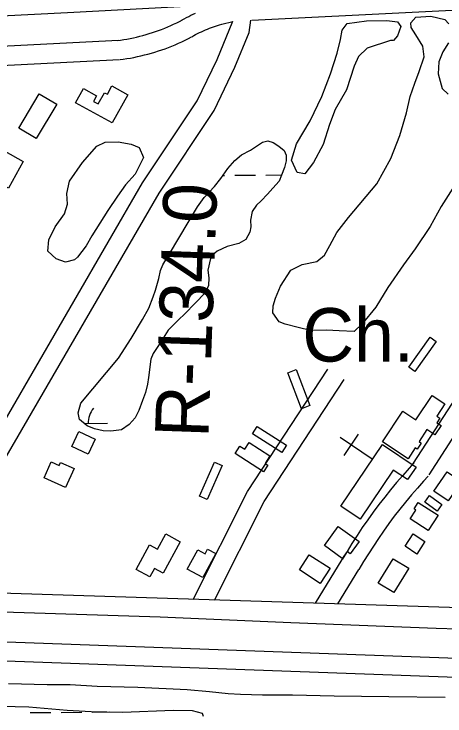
# Model space of a CAD drawing. Extents: x 3540316 to 3578335, y 553172 to 578787.
# Drawn here: x 3546594 to 3547262, y 568493 to 569583 of the extents above; entities that cross this region are included whole.
import ezdxf

# ---------------------------------------------------------------- set-up
doc = ezdxf.new("R2010")
doc.units = 0
for name, color, linetype in [('V-BLDG-OTLN', 7, 'Continuous'), ('V-LEVE-TOET', 7, 'Continuous'), ('V-RAIL-TRAK', 7, 'Continuous'), ('V-RIVR-RANG-IDEN', 7, 'Continuous'), ('V-ROAD-CNTR', 7, 'Continuous'), ('V-SITE-OTLN', 7, 'Continuous'), ('V-SITE-OTLN-IDEN', 7, 'Continuous'), ('V-SITE-VEGE', 7, 'Continuous'), ('V-SURV-LINE', 7, 'Continuous'), ('V-WETL-SWMP', 7, 'Continuous')]:
    doc.layers.add(name, color=color, linetype=linetype)

msp = doc.modelspace()

# ---------------------------------------------------------------- linework, layer by layer
at = {"layer": 'V-BLDG-OTLN'}
for points in [[(3546770.6, 569457.3), (3546746.3, 569413.5), (3546689.5, 569444.9), (3546701.7, 569467.1), (3546722.2, 569455.7), (3546717.4, 569447), (3546724.6, 569443), (3546734.3, 569460.5), (3546738.9, 569458), (3546746, 569470.9)], [(3546660.5, 569442.7), (3546628.6, 569389.2), (3546601.6, 569405.4), (3546633.4, 569458.8)], [(3546608.5, 569353.6), (3546585.7, 569312.4), (3546556.9, 569328.4), (3546579.8, 569369.5)], [(3547248.7, 569074.3), (3547215.5, 569027.7), (3547206.4, 569034.2), (3547239.6, 569080.8)], [(3547031.9, 569030.6), (3547053, 568974.8), (3547039.9, 568969.9), (3547018.9, 569025.7)], [(3547205.2, 568892.3), (3547165.5, 568918.6), (3547197, 568966.3), (3547217.4, 568952.8), (3547242.4, 568990.5), (3547262.3, 568977.3), (3547249.8, 568958.4), (3547254.5, 568955.3), (3547249.9, 568948.2), (3547256.5, 568943.8), (3547246.9, 568929.3), (3547234.5, 568937.5), (3547222.3, 568919), (3547225.8, 568916.6), (3547219.3, 568906.9), (3547216.3, 568909)], [(3546720, 568922.7), (3546708.9, 568899.4), (3546683.8, 568911.3), (3546694.9, 568934.7)], [(3547009.4, 568902.1), (3546964.1, 568931.2), (3546971.2, 568942.3), (3547016.5, 568913.2)], [(3546981, 568872), (3546937.2, 568900.4), (3546944.6, 568911.9), (3546952.1, 568907.1), (3546958.9, 568917.6), (3546991.1, 568896.8), (3546983.4, 568885), (3546987.7, 568882.3)], [(3547101.1, 568818.5), (3547165.5, 568914.5), (3547217.7, 568879.4), (3547204.6, 568859.9), (3547182.4, 568874.7), (3547131.2, 568798.3)], [(3546640.7, 568862.6), (3546651.8, 568887.3), (3546664.1, 568881.7), (3546666.4, 568886.7), (3546687.5, 568877.2), (3546674.1, 568847.5)], [(3546917.1, 568881.9), (3546893.5, 568829.1), (3546881.7, 568834.4), (3546905.3, 568887.2)], [(3547288.3, 568856.9), (3547267.5, 568826.7), (3547245.4, 568842), (3547266.1, 568872.1)], [(3547250.2, 568811), (3547231.1, 568824.8), (3547238.4, 568835.1), (3547257.6, 568821.2)], [(3547236.4, 568780.8), (3547208.3, 568798.8), (3547217.2, 568812.7), (3547214.6, 568814.4), (3547221.1, 568824.6), (3547251.8, 568804.9)], [(3547102.8, 568737.4), (3547075.4, 568757.5), (3547097.1, 568787.2), (3547129.3, 568763.6), (3547115.5, 568744.6), (3547110.7, 568748.2)], [(3546852, 568763.3), (3546825.6, 568714.6), (3546812.1, 568721.9), (3546805, 568708.8), (3546783.7, 568720.3), (3546804.4, 568758.5), (3546816.6, 568751.9), (3546829.4, 568775.5)], [(3547231.5, 568763.6), (3547219, 568744.4), (3547200.6, 568756.4), (3547213.1, 568775.6)], [(3546906.9, 568745.2), (3546886.8, 568708.1), (3546862.8, 568721.1), (3546879.1, 568751.1), (3546890.6, 568744.9), (3546894.4, 568751.9)], [(3547051.9, 568743.1), (3547084.2, 568722.4), (3547069, 568698.8), (3547036.8, 568719.6)], [(3547159, 568699.3), (3547181.9, 568737), (3547206.2, 568722.2), (3547183.4, 568684.5)]]:
    msp.add_lwpolyline(points, close=True, dxfattribs=at)
at = {"layer": 'V-LEVE-TOET'}
for points in [[(3547740.4, 568609.2), (3547603, 568614.6), (3547416.9, 568623.7), (3547248.7, 568628.6), (3547023.7, 568637.8), (3546820.6, 568646.2), (3546577.1, 568654.2), (3546379.4, 568658.5), (3546116.1, 568667.9), (3546052.5, 568669.6), (3545807.7, 568677.5), (3545748.9, 568677.1), (3545669.5, 568674.1), (3545560.7, 568664.3), (3545380.7, 568652.1), (3545183, 568637.3), (3545015.3, 568626.4), (3544792.3, 568613.1), (3544595.9, 568600.3), (3544446.6, 568588.6)], [(3546585.6, 568543.6), (3546645.8, 568541.9), (3546681.4, 568541.8), (3546723.1, 568539.5), (3546786, 568537.9), (3546862.6, 568534.1), (3546897.5, 568531.2), (3546926.2, 568527.7), (3546945.4, 568526.9), (3546979.6, 568526), (3547026.1, 568525.8), (3547090.4, 568524.2), (3547175.2, 568523.1), (3547262.7, 568522)]]:
    msp.add_lwpolyline(points, dxfattribs=at)
at = {"layer": 'V-RAIL-TRAK'}
msp.add_lwpolyline([(3544440.2, 569467.6), (3544499.8, 569470.6), (3544650.3, 569478.1), (3544767.7, 569484.7), (3544854.2, 569489.5), (3545075.2, 569500.8), (3545365.9, 569515.9), (3545593.8, 569528.5), (3545806.6, 569539.9), (3545830.1, 569541.1), (3546063.1, 569553.1), (3546369.7, 569569.5), (3546676.9, 569585.2), (3546997.1, 569602.2), (3547359.7, 569620.4), (3547619, 569632.9), (3547707.6, 569637.2)], dxfattribs=at)
at = {"layer": 'V-ROAD-CNTR'}
for points in [[(3546963.1, 569573.3), (3547470.5, 569598.4)], [(3546855, 569573.4), (3546858.2, 569575.2), (3546861.6, 569577.1), (3546865.1, 569578.9), (3546868.5, 569580.6), (3546872, 569582.3), (3546875.6, 569583.9)], [(3546427.1, 568688.2), (3546580.5, 568952), (3546793.6, 569320.3), (3546878.4, 569447.9), (3546909.3, 569512.2), (3546933.5, 569571.5)], [(3546461.2, 568687.1), (3546606.5, 568937), (3546819.1, 569304.5), (3546904.6, 569433), (3546936.7, 569500.1), (3546958.7, 569553.9), (3546961.3, 569573.2)], [(3546755, 569541.7), (3546759.3, 569542.2), (3546764.3, 569543), (3546769.3, 569543.8), (3546774.3, 569544.8), (3546779.3, 569545.8), (3546784.2, 569546.9), (3546789.2, 569548.1), (3546794.1, 569549.4), (3546799, 569550.7), (3546803.8, 569552.2), (3546808.7, 569553.7), (3546813.5, 569555.4), (3546818.3, 569557), (3546823, 569558.8), (3546827.8, 569560.7), (3546832.5, 569562.7), (3546837.1, 569564.7), (3546841.7, 569566.8), (3546846.4, 569569), (3546850.9, 569571.2), (3546855.5, 569573.7)], [(3546869.9, 569547.4), (3546872.8, 569549), (3546875.7, 569550.6), (3546878.7, 569552.2), (3546881.7, 569553.7), (3546884.8, 569555.1), (3546887.8, 569556.5), (3546890.9, 569557.9), (3546894, 569559.2), (3546897.1, 569560.4), (3546900.3, 569561.6), (3546903.4, 569562.7), (3546906.6, 569563.8), (3546909.8, 569564.8), (3546913, 569565.7), (3546916.3, 569566.7), (3546933.3, 569571.1)], [(3544779, 569435.5), (3546311.5, 569519), (3546756.2, 569541.8)], [(3546759, 569511.9), (3546763.5, 569512.5), (3546769, 569513.4), (3546774.6, 569514.3), (3546780.1, 569515.3), (3546785.6, 569516.5), (3546791, 569517.7), (3546796.4, 569519), (3546801.9, 569520.4), (3546807.3, 569521.9), (3546812.7, 569523.5), (3546818, 569525.2), (3546823.3, 569527), (3546828.6, 569528.8), (3546833.9, 569530.8), (3546839.1, 569532.9), (3546844.2, 569535), (3546849.4, 569537.3), (3546854.5, 569539.6), (3546859.5, 569542), (3546864.5, 569544.5), (3546869.4, 569547.1)], [(3546492.7, 569498.3), (3546757.8, 569511.8)], [(3547212.8, 568883.7), (3547274, 568978.7), (3547337.1, 569071.9), (3547340.9, 569077.3)], [(3547238, 568867.4), (3547299, 568962.2), (3547361.8, 569054.8), (3547365.5, 569060.1)], [(3546872, 568674), (3546956.2, 568841.2), (3547080.9, 569031.5)], [(3546905, 568672.9), (3546982.3, 568826.1), (3547106, 569015.1)], [(3547214.4, 568885.7), (3547206.8, 568877.5), (3547197.1, 568866.5), (3547187.5, 568855.4), (3547178.1, 568844.1), (3547169, 568832.7), (3547160, 568821.1), (3547151.2, 568809.2), (3547142.7, 568797.4), (3547134.3, 568785.3), (3547126.2, 568773), (3547118.3, 568760.8), (3547110.6, 568748.3), (3547103.2, 568735.7)], [(3547236.4, 568865.4), (3547229, 568857.4), (3547219.7, 568846.8), (3547210.4, 568836.1), (3547201.4, 568825.1), (3547192.5, 568814.1), (3547183.9, 568803), (3547175.5, 568791.6), (3547167.2, 568780.1), (3547159.2, 568768.5), (3547151.4, 568756.6), (3547143.7, 568744.7), (3547136.3, 568732.8), (3547129, 568720.5)], [(3547061.6, 568668), (3547103.3, 568735.9)], [(3547096.1, 568666.9), (3547128.9, 568720.2)], [(3548203.3, 568619.8), (3547285.4, 568660.8), (3545892.6, 568705.2)]]:
    msp.add_lwpolyline(points, dxfattribs=at)
at = {"layer": 'V-SITE-OTLN'}
for p, q in [((3547149.7, 568891.5), (3547100.2, 568925.3)), ((3547127.9, 568930.6), (3547105.4, 568897.5))]:
    msp.add_line(p, q, dxfattribs=at)
at = {"layer": 'V-SITE-VEGE'}
for points in [[(3547278.3, 569317.8), (3547256.7, 569284), (3547239.3, 569253), (3547216.4, 569217.9), (3547198.3, 569193.1), (3547174, 569158), (3547155.2, 569127.7), (3547134.3, 569101.5), (3547121.8, 569089.9), (3547098.4, 569090.7), (3547079, 569092.1), (3547054.2, 569091.5), (3547034.8, 569095.8), (3547014.8, 569101.4), (3547005.2, 569104.9), (3546995.6, 569118.8), (3546996.3, 569129.8), (3546999.8, 569141.5), (3547007.5, 569160.1), (3547023.5, 569184.9), (3547040.8, 569193.8), (3547063.6, 569198.6), (3547075.4, 569208.2), (3547083.8, 569223.3), (3547094.9, 569243.3), (3547113, 569266.7), (3547156.7, 569319), (3547178.3, 569358.3), (3547192.3, 569394.1), (3547202.8, 569429.3), (3547208.5, 569454.8), (3547215.5, 569475.5), (3547222.4, 569493.5), (3547230.1, 569516.2), (3547228.2, 569532.8), (3547217.2, 569550.1), (3547210.3, 569561.9), (3547209.7, 569568.8), (3547217.3, 569577.7), (3547240.8, 569579), (3547262.2, 569574.1), (3547268.4, 569567.1)], [(3547268.2, 569538.1), (3547259.2, 569523.7), (3547252.9, 569508.5), (3547252.1, 569489.9), (3547258.2, 569467), (3547267.2, 569458)]]:
    msp.add_lwpolyline(points, dxfattribs=at)
for points in [[(3547177.8, 569541.3), (3547141.8, 569529.7), (3547128.6, 569516.7), (3547121.6, 569501.5), (3547109.7, 569465), (3547092.3, 569434.6), (3547083.2, 569411.2), (3547073.4, 569380.2), (3547058.8, 569351.9), (3547044.9, 569334.7), (3547033.2, 569336.8), (3547024.3, 569355.5), (3547032, 569381), (3547053.6, 569416.9), (3547071.7, 569454.8), (3547085, 569489.9), (3547095.5, 569521.7), (3547100.4, 569543), (3547103.3, 569557.5), (3547110.9, 569567.9), (3547140.6, 569571.9), (3547172.4, 569572.4), (3547189, 569570.3), (3547193.8, 569563.3), (3547188.9, 569548.9), (3547182.6, 569541.3)], [(3546795, 569360), (3546781.8, 569333.8), (3546767.2, 569317.3), (3546754.7, 569300.1), (3546739.4, 569277.4), (3546715, 569238.1), (3546706, 569223), (3546692.8, 569205.1), (3546687.9, 569201), (3546674.1, 569197.6), (3546659.6, 569202.5), (3546646.5, 569214.3), (3546648, 569232.2), (3546657.8, 569252.2), (3546672.3, 569272.2), (3546677.3, 569287.3), (3546675.9, 569303.9), (3546680.2, 569323.2), (3546700.3, 569352.2), (3546722.6, 569377.6), (3546735.7, 569383.8), (3546755.7, 569384.4), (3546775.8, 569380.8), (3546788.2, 569375.2)]]:
    msp.add_lwpolyline(points, close=True, dxfattribs=at)
at = {"layer": 'V-SURV-LINE'}
for points in [[(3545755.6, 568637.9), (3548250.8, 568547.7)], [(3548249.7, 568517.8), (3545754.5, 568607.9)]]:
    msp.add_lwpolyline(points, dxfattribs=at)
at = {"layer": 'V-WETL-SWMP'}
for p, q in [((3546918.2, 569332.1), (3546920.8, 569332.1)), ((3546936.8, 569332.2), (3546968.8, 569332.5)), ((3546984.8, 569332.6), (3547009.1, 569332.8)), ((3546703.1, 568947), (3546739.1, 568947.3)), ((3546619.2, 568498.3), (3546651.2, 568498.5)), ((3546667.2, 568498.6), (3546699.2, 568498.9)), ((3546715.2, 568499), (3546742.1, 568499.2))]:
    msp.add_line(p, q, dxfattribs=at)
msp.add_lwpolyline([(3546806.2, 569046.9), (3546802.6, 569018.5), (3546801.2, 569008.1), (3546798.3, 568995), (3546793.4, 568982.5), (3546787.8, 568967.3), (3546782.2, 568955.6), (3546772.5, 568945.2), (3546760.7, 568937), (3546744.1, 568935), (3546732.3, 568935.7), (3546719.1, 568938.6), (3546707.4, 568943.5), (3546695.7, 568953.2), (3546693.6, 568963.6), (3546697.9, 568978.8), (3546756.3, 569048.5), (3546775.9, 569078.8), (3546793.3, 569108.5), (3546803.1, 569125.8), (3546810.1, 569143.8), (3546813.6, 569154.1), (3546818.5, 569172.1), (3546821.3, 569184.6), (3546824.8, 569193.5), (3546835.3, 569210.1), (3546878.6, 569283.3), (3546889, 569297.8), (3546905, 569315), (3546914.8, 569327.4), (3546925.9, 569342.6), (3546936.4, 569355), (3546946.8, 569364), (3546960.7, 569371.5), (3546979.4, 569383.9), (3546987.7, 569386), (3546996, 569383.1), (3547005, 569377.6), (3547013.3, 569370.6), (3547016, 569363.7), (3547016, 569354.7), (3547013.8, 569344.3), (3547008.9, 569332.6), (3547005.4, 569322.9), (3546995.7, 569312.5), (3546987.3, 569302.9), (3546977.6, 569292.5), (3546970, 569285.7), (3546963.7, 569276), (3546960.9, 569262.8), (3546961.5, 569252.5), (3546960.1, 569244.2), (3546953.8, 569232.4), (3546942.7, 569226.2), (3546924.7, 569221.5), (3546909.4, 569214.6), (3546901.8, 569208.4), (3546899, 569202.9), (3546894.7, 569184.9), (3546896.1, 569173.1), (3546896, 569161.4), (3546891.1, 569150.3), (3546874.4, 569133.1), (3546859.8, 569117.9), (3546848.7, 569107.6), (3546833.4, 569091.7), (3546820.1, 569071), (3546809.7, 569055.8)], close=True, dxfattribs=at)
msp.add_lwpolyline([(3546014, 568521.4), (3546059.1, 568515), (3546099.4, 568511.4), (3546139.1, 568511.9), (3546187.7, 568515.8), (3546262.9, 568516.1), (3546363.5, 568512.3), (3546446.2, 568511.9), (3546531.7, 568509.4), (3546617.2, 568507), (3546676.7, 568501.9), (3546713.6, 568499.7), (3546762.9, 568498.8), (3546840.9, 568501.9), (3546870.3, 568501.7), (3546886, 568497.6), (3546887.3, 568492.8)], dxfattribs=at)
msp.add_arc((3546744.4, 568947.8), 35.2, 139.6699, 181.2135, dxfattribs=at)

# ---------------------------------------------------------------- texts
at = {"layer": 'V-RIVR-RANG-IDEN'}
msp.add_text('R-134.0', height=83, rotation=87.9832, dxfattribs=at).set_placement((3546895.5, 568924))
at = {"layer": 'V-SITE-OTLN-IDEN'}
msp.add_text('Ch.', height=83, dxfattribs=at).set_placement((3547041.3, 569043.1))

doc.saveas('drawing.dxf')
